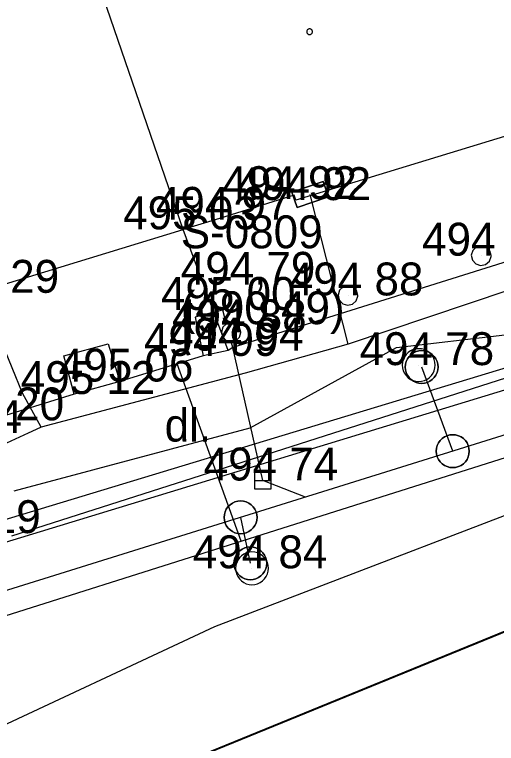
# Model space of a CAD drawing. Extents: x -695326 to -694942, y -1122979 to -1122738.
# Drawn here: x -695117.34 to -695102.7, y -1122949.89 to -1122927.72 of the extents above; entities that cross this region are included whole.
import ezdxf

# ---------------------------------------------------------------- set-up
doc = ezdxf.new("R2010")
doc.units = 0
for name, color, linetype in [('Budovy', 7, 'Continuous'), ('Level 30', 7, 'Continuous'), ('Level 35', 7, 'Continuous'), ('Level 36', 7, 'Continuous'), ('Level 38', 7, 'Continuous'), ('Level 42', 7, 'Continuous'), ('Level 44', 7, 'Continuous'), ('Level 48', 7, 'Continuous'), ('Level 51', 7, 'Continuous'), ('Level 53', 7, 'Continuous'), ('Popisy', 7, 'Continuous'), ('Rozhraní ploch', 7, 'Continuous')]:
    doc.layers.add(name, color=color, linetype=linetype)

msp = doc.modelspace()

# ---------------------------------------------------------------- linework, layer by layer
at = {"layer": 'Budovy'}
for p, q in [((-695112.22, -1122934.25), (-695116.37, -1122922.16)), ((-695108.38, -1122928.24), (-695108.38, -1122928.24)), ((-695108.847, -1122933.21), (-695111.25, -1122933.96)), ((-695111.25, -1122933.96), (-695112.22, -1122934.25)), ((-695111.285, -1122936.77), (-695112.22, -1122934.25)), ((-695110.85, -1122937.94), (-695111.285, -1122936.77))]:
    msp.add_line(p, q, dxfattribs=at)
for points in [[(-695079.71, -1122928), (-695090.83, -1122931.54), (-695098.92, -1122934.14), (-695110.716, -1122937.846), (-695110.85, -1122937.94), (-695111.61, -1122938.1), (-695114.15, -1122938.88), (-695115.53, -1122939.26), (-695118.09, -1122940.06), (-695119.41, -1122940.45), (-695122, -1122941.3), (-695122.89, -1122941.6), (-695123.98, -1122941.87), (-695126.43, -1122942.62), (-695127.9, -1122943.06), (-695131.24, -1122944.1), (-695132.25, -1122944.47), (-695132.43, -1122944.22), (-695135.83, -1122944.84), (-695136.49, -1122944.96), (-695139.66, -1122945.47), (-695140.32, -1122945.55), (-695143.21, -1122945.96), (-695143.91, -1122946.04)], [(-695108.292, -1122928.24), (-695108.294, -1122928.225), (-695108.298, -1122928.21), (-695108.304, -1122928.196), (-695108.313, -1122928.184), (-695108.324, -1122928.173), (-695108.336, -1122928.164), (-695108.35, -1122928.158), (-695108.365, -1122928.154), (-695108.38, -1122928.152), (-695108.395, -1122928.154), (-695108.41, -1122928.158), (-695108.424, -1122928.164), (-695108.436, -1122928.173), (-695108.447, -1122928.184), (-695108.456, -1122928.196), (-695108.462, -1122928.21), (-695108.466, -1122928.225), (-695108.467, -1122928.24), (-695108.466, -1122928.255), (-695108.462, -1122928.27), (-695108.456, -1122928.284), (-695108.447, -1122928.296), (-695108.436, -1122928.307), (-695108.424, -1122928.316), (-695108.41, -1122928.322), (-695108.395, -1122928.326), (-695108.38, -1122928.328), (-695108.365, -1122928.326), (-695108.35, -1122928.322), (-695108.336, -1122928.316), (-695108.324, -1122928.307), (-695108.313, -1122928.296), (-695108.304, -1122928.284), (-695108.298, -1122928.27), (-695108.294, -1122928.255), (-695108.292, -1122928.24)], [(-695100.16, -1122930.73), (-695108.8, -1122933.36), (-695108.847, -1122933.21)], [(-695133.69, -1122940.84), (-695124.344, -1122937.971), (-695112.22, -1122934.25)], [(-695102.858, -1122935.05), (-695102.897, -1122934.901), (-695103.005, -1122934.791), (-695103.153, -1122934.748), (-695103.303, -1122934.784), (-695103.416, -1122934.889), (-695103.462, -1122935.036), (-695103.43, -1122935.187), (-695103.327, -1122935.302), (-695103.181, -1122935.352), (-695103.03, -1122935.323), (-695102.912, -1122935.223), (-695102.859, -1122935.078), (-695102.858, -1122935.05)], [(-695106.91, -1122936.26), (-695106.949, -1122936.111), (-695107.057, -1122936.002), (-695107.205, -1122935.96), (-695107.354, -1122935.997), (-695107.465, -1122936.102), (-695107.51, -1122936.249), (-695107.476, -1122936.399), (-695107.372, -1122936.513), (-695107.226, -1122936.56), (-695107.076, -1122936.528), (-695106.96, -1122936.427), (-695106.911, -1122936.281), (-695106.91, -1122936.26)], [(-695110.465, -1122937.38), (-695110.504, -1122937.233), (-695110.611, -1122937.125), (-695110.758, -1122937.085), (-695110.906, -1122937.123), (-695111.015, -1122937.23), (-695111.055, -1122937.377), (-695111.018, -1122937.525), (-695110.911, -1122937.634), (-695110.765, -1122937.675), (-695110.617, -1122937.638), (-695110.507, -1122937.533), (-695110.465, -1122937.386), (-695110.465, -1122937.38)]]:
    msp.add_lwpolyline(points, dxfattribs=at)
at = {"layer": 'Level 30'}
for p, q in [((-695105.06, -1122938.38), (-695105.06, -1122938.38)), ((-695109.8, -1122941.89), (-695109.8, -1122941.89)), ((-695110.13, -1122944.56), (-695110.13, -1122944.56))]:
    msp.add_line(p, q, dxfattribs=at)
for points in [[(-695104.56, -1122938.38), (-695104.568, -1122938.293), (-695104.59, -1122938.209), (-695104.627, -1122938.13), (-695104.677, -1122938.059), (-695104.739, -1122937.997), (-695104.81, -1122937.947), (-695104.889, -1122937.91), (-695104.973, -1122937.888), (-695105.06, -1122937.88), (-695105.147, -1122937.888), (-695105.231, -1122937.91), (-695105.31, -1122937.947), (-695105.381, -1122937.997), (-695105.443, -1122938.059), (-695105.493, -1122938.13), (-695105.53, -1122938.209), (-695105.552, -1122938.293), (-695105.56, -1122938.38), (-695105.552, -1122938.467), (-695105.53, -1122938.551), (-695105.493, -1122938.63), (-695105.443, -1122938.701), (-695105.381, -1122938.763), (-695105.31, -1122938.813), (-695105.231, -1122938.85), (-695105.147, -1122938.872), (-695105.06, -1122938.88), (-695104.973, -1122938.872), (-695104.889, -1122938.85), (-695104.81, -1122938.813), (-695104.739, -1122938.763), (-695104.677, -1122938.701), (-695104.627, -1122938.63), (-695104.59, -1122938.551), (-695104.568, -1122938.467), (-695104.56, -1122938.38)], [(-695110.05, -1122942.141), (-695109.55, -1122942.141), (-695109.55, -1122941.64), (-695110.05, -1122941.64), (-695110.05, -1122942.141)], [(-695110.05, -1122941.89), (-695109.55, -1122941.89)], [(-695109.63, -1122944.56), (-695109.638, -1122944.473), (-695109.66, -1122944.389), (-695109.697, -1122944.31), (-695109.747, -1122944.239), (-695109.809, -1122944.177), (-695109.88, -1122944.127), (-695109.959, -1122944.09), (-695110.043, -1122944.068), (-695110.13, -1122944.06), (-695110.217, -1122944.068), (-695110.301, -1122944.09), (-695110.38, -1122944.127), (-695110.451, -1122944.177), (-695110.513, -1122944.239), (-695110.563, -1122944.31), (-695110.6, -1122944.389), (-695110.622, -1122944.473), (-695110.63, -1122944.56), (-695110.622, -1122944.647), (-695110.6, -1122944.731), (-695110.563, -1122944.81), (-695110.513, -1122944.881), (-695110.451, -1122944.943), (-695110.38, -1122944.993), (-695110.301, -1122945.03), (-695110.217, -1122945.052), (-695110.13, -1122945.06), (-695110.043, -1122945.052), (-695109.959, -1122945.03), (-695109.88, -1122944.993), (-695109.809, -1122944.943), (-695109.747, -1122944.881), (-695109.697, -1122944.81), (-695109.66, -1122944.731), (-695109.638, -1122944.647), (-695109.63, -1122944.56)]]:
    msp.add_lwpolyline(points, dxfattribs=at)
at = {"layer": 'Level 35'}
for p, q in [((-695109.8, -1122941.89), (-695110.716, -1122937.846)), ((-695110.459, -1122943.731), (-695112.4, -1122938.342)), ((-695108.503, -1122942.397), (-695109.8, -1122941.89))]:
    msp.add_line(p, q, dxfattribs=at)
for points in [[(-695122.183, -1122978.845), (-695130.45, -1122957.93), (-695095.39, -1122943.61), (-695072.77, -1122934.37), (-695099.42, -1122862.69)], [(-695131.247, -1122978.864), (-695132.65, -1122975.94), (-695157.61, -1122969.63), (-695140.47, -1122958.8), (-695136.63, -1122948.53), (-695119.01, -1122943.49), (-695100.79, -1122937.97), (-695082.69, -1122932.49), (-695067.48, -1122925.68), (-695054.28, -1122919.15), (-695039.04, -1122911.54), (-695024.78, -1122904.45), (-695010.56, -1122897.35), (-694996.02, -1122890.13), (-694983.12, -1122883.66), (-694965.65, -1122874.99), (-694952.69, -1122868.61), (-694948.627, -1122866.586)]]:
    msp.add_lwpolyline(points, dxfattribs=at)
at = {"layer": 'Level 36'}
msp.add_line((-695107.21, -1122937.74), (-695108.36, -1122933.19), dxfattribs=at)
for points in [[(-695116.54, -1122940.27), (-695117.1, -1122939.23), (-695118.37, -1122936.15), (-695119.01, -1122935.28), (-695120.18, -1122934.18), (-695121.96, -1122932.91), (-695123.66, -1122931.63), (-695125.78, -1122929.26), (-695131.63, -1122915.78), (-695138.28, -1122897.41), (-695139.21, -1122893.87), (-695140.47, -1122890.41), (-695137.56, -1122889.82), (-695139.04, -1122888.31), (-695142.02, -1122887.5), (-695144.72, -1122888.73), (-695149.49, -1122892.05), (-695153.73, -1122894.4), (-695153.68, -1122895.82), (-695153.97, -1122895.96)], [(-695117.36, -1122942.2), (-695110.18, -1122940.29), (-695105.74, -1122937.84), (-695102.44, -1122937.46), (-695099.62, -1122936.57), (-695100.53, -1122930.65)], [(-695095.52, -1122933.96), (-695099.88, -1122935.28), (-695107.21, -1122937.74)], [(-695134.34, -1122973.03), (-695133.962, -1122972.86), (-695138.962, -1122954.566), (-695138.77, -1122954.48), (-695126.25, -1122948.73), (-695098.58, -1122939.97), (-695083.17, -1122935.25)], [(-695134.55, -1122961.53), (-695132.51, -1122957.25), (-695132.03, -1122956.26), (-695129.88, -1122955.26), (-695122.6, -1122951.79), (-695118.68, -1122949.8), (-695111.26, -1122946.33), (-695098.73, -1122941.53), (-695092.08, -1122939.09), (-695082.99, -1122935.78)], [(-695107.21, -1122937.74), (-695110.34, -1122938.63), (-695116.54, -1122940.27)], [(-695116.54, -1122940.27), (-695119.05, -1122941.42), (-695121.11, -1122942.31), (-695126.12, -1122943.45), (-695131.24, -1122945.19), (-695138.5, -1122946.26), (-695142.44, -1122946.62), (-695144.4, -1122946.41), (-695145.82, -1122943.15), (-695146.18, -1122941.37)]]:
    msp.add_lwpolyline(points, dxfattribs=at)
at = {"layer": 'Level 38'}
for p, q in [((-695104.026, -1122940.998), (-695104.97, -1122938.439)), ((-695110.476, -1122943.013), (-695110.18, -1122944.41))]:
    msp.add_line(p, q, dxfattribs=at)
msp.add_lwpolyline([(-695082.58, -1122934.3), (-695132.114, -1122949.771), (-695137.17, -1122949.78)], dxfattribs=at)
at = {"layer": 'Level 42'}
msp.add_line((-695072.77, -1122934.36), (-695130.4, -1122957.89), dxfattribs=at)
at = {"layer": 'Level 44'}
for p, q in [((-695108.36, -1122933.19), (-695108.36, -1122933.19)), ((-695104.97, -1122938.439), (-695104.97, -1122938.439)), ((-695104.026, -1122940.998), (-695104.026, -1122940.998)), ((-695110.476, -1122943.013), (-695110.476, -1122943.013)), ((-695110.18, -1122944.41), (-695110.18, -1122944.41))]:
    msp.add_line(p, q, dxfattribs=at)
for points in [[(-695108.752, -1122933.589), (-695107.806, -1122933.264), (-695107.968, -1122932.791), (-695108.914, -1122933.116), (-695108.752, -1122933.589)], [(-695104.47, -1122938.439), (-695104.478, -1122938.352), (-695104.5, -1122938.268), (-695104.537, -1122938.189), (-695104.587, -1122938.118), (-695104.649, -1122938.056), (-695104.72, -1122938.006), (-695104.799, -1122937.969), (-695104.883, -1122937.947), (-695104.97, -1122937.939), (-695105.057, -1122937.947), (-695105.141, -1122937.969), (-695105.22, -1122938.006), (-695105.291, -1122938.056), (-695105.353, -1122938.118), (-695105.403, -1122938.189), (-695105.44, -1122938.268), (-695105.462, -1122938.352), (-695105.47, -1122938.439), (-695105.462, -1122938.526), (-695105.44, -1122938.61), (-695105.403, -1122938.689), (-695105.353, -1122938.76), (-695105.291, -1122938.822), (-695105.22, -1122938.872), (-695105.141, -1122938.909), (-695105.057, -1122938.931), (-695104.97, -1122938.939), (-695104.883, -1122938.931), (-695104.799, -1122938.909), (-695104.72, -1122938.872), (-695104.649, -1122938.822), (-695104.587, -1122938.76), (-695104.537, -1122938.689), (-695104.5, -1122938.61), (-695104.478, -1122938.526), (-695104.47, -1122938.439)], [(-695103.526, -1122940.998), (-695103.534, -1122940.911), (-695103.556, -1122940.827), (-695103.593, -1122940.748), (-695103.643, -1122940.677), (-695103.705, -1122940.615), (-695103.776, -1122940.565), (-695103.855, -1122940.528), (-695103.939, -1122940.506), (-695104.026, -1122940.498), (-695104.113, -1122940.506), (-695104.197, -1122940.528), (-695104.276, -1122940.565), (-695104.347, -1122940.615), (-695104.409, -1122940.677), (-695104.459, -1122940.748), (-695104.496, -1122940.827), (-695104.518, -1122940.911), (-695104.526, -1122940.998), (-695104.518, -1122941.085), (-695104.496, -1122941.169), (-695104.459, -1122941.248), (-695104.409, -1122941.319), (-695104.347, -1122941.381), (-695104.276, -1122941.431), (-695104.197, -1122941.468), (-695104.113, -1122941.49), (-695104.026, -1122941.498), (-695103.939, -1122941.49), (-695103.855, -1122941.468), (-695103.776, -1122941.431), (-695103.705, -1122941.381), (-695103.643, -1122941.319), (-695103.593, -1122941.248), (-695103.556, -1122941.169), (-695103.534, -1122941.085), (-695103.526, -1122940.998)], [(-695109.976, -1122943.013), (-695109.984, -1122942.926), (-695110.006, -1122942.842), (-695110.043, -1122942.763), (-695110.093, -1122942.692), (-695110.155, -1122942.63), (-695110.226, -1122942.58), (-695110.305, -1122942.543), (-695110.389, -1122942.521), (-695110.476, -1122942.513), (-695110.563, -1122942.521), (-695110.647, -1122942.543), (-695110.726, -1122942.58), (-695110.797, -1122942.63), (-695110.859, -1122942.692), (-695110.909, -1122942.763), (-695110.946, -1122942.842), (-695110.968, -1122942.926), (-695110.976, -1122943.013), (-695110.968, -1122943.1), (-695110.946, -1122943.184), (-695110.909, -1122943.263), (-695110.859, -1122943.334), (-695110.797, -1122943.396), (-695110.726, -1122943.446), (-695110.647, -1122943.483), (-695110.563, -1122943.505), (-695110.476, -1122943.513), (-695110.389, -1122943.505), (-695110.305, -1122943.483), (-695110.226, -1122943.446), (-695110.155, -1122943.396), (-695110.093, -1122943.334), (-695110.043, -1122943.263), (-695110.006, -1122943.184), (-695109.984, -1122943.1), (-695109.976, -1122943.013)], [(-695109.68, -1122944.41), (-695109.688, -1122944.323), (-695109.71, -1122944.239), (-695109.747, -1122944.16), (-695109.797, -1122944.089), (-695109.859, -1122944.027), (-695109.93, -1122943.977), (-695110.009, -1122943.94), (-695110.093, -1122943.918), (-695110.18, -1122943.91), (-695110.267, -1122943.918), (-695110.351, -1122943.94), (-695110.43, -1122943.977), (-695110.501, -1122944.027), (-695110.563, -1122944.089), (-695110.613, -1122944.16), (-695110.65, -1122944.239), (-695110.672, -1122944.323), (-695110.68, -1122944.41), (-695110.672, -1122944.497), (-695110.65, -1122944.581), (-695110.613, -1122944.66), (-695110.563, -1122944.731), (-695110.501, -1122944.793), (-695110.43, -1122944.843), (-695110.351, -1122944.88), (-695110.267, -1122944.902), (-695110.18, -1122944.91), (-695110.093, -1122944.902), (-695110.009, -1122944.88), (-695109.93, -1122944.843), (-695109.859, -1122944.793), (-695109.797, -1122944.731), (-695109.747, -1122944.66), (-695109.71, -1122944.581), (-695109.688, -1122944.497), (-695109.68, -1122944.41)]]:
    msp.add_lwpolyline(points, dxfattribs=at)
for points in [[(-695107.806, -1122933.264), (-695108.752, -1122933.589), (-695108.914, -1122933.116), (-695107.968, -1122932.791)], [(-695104.883, -1122938.931), (-695104.97, -1122938.939), (-695105.057, -1122938.931), (-695105.141, -1122938.909), (-695105.22, -1122938.872), (-695105.291, -1122938.822), (-695105.353, -1122938.76), (-695105.403, -1122938.689), (-695105.44, -1122938.61), (-695105.462, -1122938.526), (-695105.47, -1122938.439), (-695105.462, -1122938.352), (-695105.44, -1122938.268), (-695105.403, -1122938.189), (-695105.353, -1122938.118), (-695105.291, -1122938.056), (-695105.22, -1122938.006), (-695105.141, -1122937.969), (-695105.057, -1122937.947), (-695104.97, -1122937.939), (-695104.883, -1122937.947), (-695104.799, -1122937.969), (-695104.72, -1122938.006), (-695104.649, -1122938.056), (-695104.587, -1122938.118), (-695104.537, -1122938.189), (-695104.5, -1122938.268), (-695104.478, -1122938.352), (-695104.47, -1122938.439), (-695104.478, -1122938.526), (-695104.5, -1122938.61), (-695104.537, -1122938.689), (-695104.587, -1122938.76), (-695104.649, -1122938.822), (-695104.72, -1122938.872), (-695104.799, -1122938.909)], [(-695103.939, -1122941.49), (-695104.026, -1122941.498), (-695104.113, -1122941.49), (-695104.197, -1122941.468), (-695104.276, -1122941.431), (-695104.347, -1122941.381), (-695104.409, -1122941.319), (-695104.459, -1122941.248), (-695104.496, -1122941.169), (-695104.518, -1122941.085), (-695104.526, -1122940.998), (-695104.518, -1122940.911), (-695104.496, -1122940.827), (-695104.459, -1122940.748), (-695104.409, -1122940.677), (-695104.347, -1122940.615), (-695104.276, -1122940.565), (-695104.197, -1122940.528), (-695104.113, -1122940.506), (-695104.026, -1122940.498), (-695103.939, -1122940.506), (-695103.855, -1122940.528), (-695103.776, -1122940.565), (-695103.705, -1122940.615), (-695103.643, -1122940.677), (-695103.593, -1122940.748), (-695103.556, -1122940.827), (-695103.534, -1122940.911), (-695103.526, -1122940.998), (-695103.534, -1122941.085), (-695103.556, -1122941.169), (-695103.593, -1122941.248), (-695103.643, -1122941.319), (-695103.705, -1122941.381), (-695103.776, -1122941.431), (-695103.855, -1122941.468)], [(-695110.389, -1122943.505), (-695110.476, -1122943.513), (-695110.563, -1122943.505), (-695110.647, -1122943.483), (-695110.726, -1122943.446), (-695110.797, -1122943.396), (-695110.859, -1122943.334), (-695110.909, -1122943.263), (-695110.946, -1122943.184), (-695110.968, -1122943.1), (-695110.976, -1122943.013), (-695110.968, -1122942.926), (-695110.946, -1122942.842), (-695110.909, -1122942.763), (-695110.859, -1122942.692), (-695110.797, -1122942.63), (-695110.726, -1122942.58), (-695110.647, -1122942.543), (-695110.563, -1122942.521), (-695110.476, -1122942.513), (-695110.389, -1122942.521), (-695110.305, -1122942.543), (-695110.226, -1122942.58), (-695110.155, -1122942.63), (-695110.093, -1122942.692), (-695110.043, -1122942.763), (-695110.006, -1122942.842), (-695109.984, -1122942.926), (-695109.976, -1122943.013), (-695109.984, -1122943.1), (-695110.006, -1122943.184), (-695110.043, -1122943.263), (-695110.093, -1122943.334), (-695110.155, -1122943.396), (-695110.226, -1122943.446), (-695110.305, -1122943.483)], [(-695110.093, -1122944.902), (-695110.18, -1122944.91), (-695110.267, -1122944.902), (-695110.351, -1122944.88), (-695110.43, -1122944.843), (-695110.501, -1122944.793), (-695110.563, -1122944.731), (-695110.613, -1122944.66), (-695110.65, -1122944.581), (-695110.672, -1122944.497), (-695110.68, -1122944.41), (-695110.672, -1122944.323), (-695110.65, -1122944.239), (-695110.613, -1122944.16), (-695110.563, -1122944.089), (-695110.501, -1122944.027), (-695110.43, -1122943.977), (-695110.351, -1122943.94), (-695110.267, -1122943.918), (-695110.18, -1122943.91), (-695110.093, -1122943.918), (-695110.009, -1122943.94), (-695109.93, -1122943.977), (-695109.859, -1122944.027), (-695109.797, -1122944.089), (-695109.747, -1122944.16), (-695109.71, -1122944.239), (-695109.688, -1122944.323), (-695109.68, -1122944.41), (-695109.688, -1122944.497), (-695109.71, -1122944.581), (-695109.747, -1122944.66), (-695109.797, -1122944.731), (-695109.859, -1122944.793), (-695109.93, -1122944.843), (-695110.009, -1122944.88)]]:
    msp.add_lwpolyline(points, close=True, dxfattribs=at)
at = {"layer": 'Level 51'}
for p, q in [((-695109.23, -1122933.33), (-695109.23, -1122933.33)), ((-695108.8, -1122933.36), (-695108.8, -1122933.36)), ((-695111.25, -1122933.96), (-695111.25, -1122933.96)), ((-695112.22, -1122934.25), (-695112.22, -1122934.25)), ((-695103.16, -1122935.05), (-695103.16, -1122935.05)), ((-695107.21, -1122936.26), (-695107.21, -1122936.26)), ((-695111.03, -1122936.7), (-695111.03, -1122936.7)), ((-695110.76, -1122937.38), (-695110.76, -1122937.38)), ((-695110.85, -1122937.94), (-695110.85, -1122937.94)), ((-695111.61, -1122938.1), (-695111.61, -1122938.1)), ((-695105.06, -1122938.38), (-695105.06, -1122938.38)), ((-695114.15, -1122938.88), (-695114.15, -1122938.88)), ((-695115.53, -1122939.26), (-695115.53, -1122939.26)), ((-695109.8, -1122941.89), (-695109.8, -1122941.89)), ((-695110.13, -1122944.56), (-695110.13, -1122944.56))]:
    msp.add_line(p, q, dxfattribs=at)
at = {"layer": 'Level 53'}
msp.add_line((-695080.16, -1122931.66), (-695117.44, -1122943.58), dxfattribs=at)
at = {"layer": 'Rozhraní ploch'}
msp.add_line((-695110.716, -1122937.846), (-695110.76, -1122937.675), dxfattribs=at)
for points in [[(-695078.88, -1122927.75), (-695078.67, -1122928.75), (-695079.45, -1122931.14), (-695081.55, -1122932.72), (-695097.9, -1122937.75), (-695120.76, -1122944.73), (-695134.78, -1122948.87), (-695138.25, -1122948.9), (-695141.57, -1122948.15), (-695143.91, -1122946.04)], [(-695111.285, -1122936.77), (-695111.03, -1122936.7), (-695110.913, -1122937.127)], [(-695111.285, -1122936.77), (-695111.857, -1122936.926), (-695111.61, -1122938.1)], [(-695115.53, -1122939.26), (-695115.849, -1122938.103), (-695114.502, -1122937.733), (-695114.15, -1122938.88)]]:
    msp.add_lwpolyline(points, dxfattribs=at)

# ---------------------------------------------------------------- texts
at = {"layer": 'Level 48'}
for s, p in [('Š-0809', (-695112.294, -1122934.826)), ('494,79', (-695112.294, -1122935.936)), ('(490,49)', (-695112.294, -1122937.136))]:
    msp.add_text(s, height=1, dxfattribs=at).set_placement(p)
at = {"layer": 'Level 53'}
for s, p in [('494 92', (-695111.03, -1122933.33)), ('494 92', (-695110.6, -1122933.36)), ('494 97', (-695113.05, -1122933.96)), ('495 03', (-695114.043, -1122934.25)), ('494 72', (-695104.958, -1122935.05)), ('495 29', (-695120.081, -1122936.18)), ('494 88', (-695109.008, -1122936.26)), ('495 00', (-695112.896, -1122936.7)), ('494 88', (-695112.558, -1122937.38)), ('494 94', (-695112.65, -1122937.94)), ('494 99', (-695113.414, -1122938.1)), ('494 78', (-695106.858, -1122938.38)), ('495 06', (-695116.001, -1122938.88)), ('495 12', (-695117.157, -1122939.26)), ('495 20', (-695119.93, -1122940.06)), ('495 24', (-695121.208, -1122940.45)), ('494 74', (-695111.598, -1122941.89)), ('495 19', (-695120.641, -1122943.49)), ('494 84', (-695111.928, -1122944.56))]:
    msp.add_text(s, height=1, dxfattribs=at).set_placement(p)
at = {"layer": 'Popisy'}
msp.add_text('dl.', height=1, dxfattribs=at).set_placement((-695112.784, -1122940.705))

doc.saveas('drawing.dxf')
